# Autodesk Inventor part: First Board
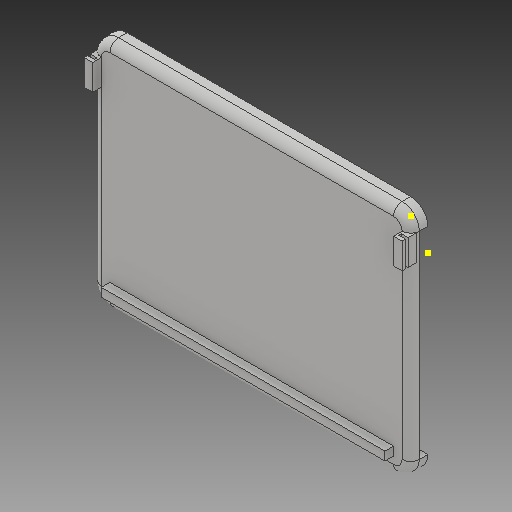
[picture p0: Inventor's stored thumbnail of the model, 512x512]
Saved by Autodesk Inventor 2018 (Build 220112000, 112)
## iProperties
Created: 2017-07
Part Number: First Board
Material: Generic
Document SubType Name: Modeling
Designer: 17046589
Density: 1 g/cm^3
Appearance: Default
Mass: 1188.89 g
Surface Area: 2386.5 cm^2
Volume: 1188.89 cm^3
Author: 17046589
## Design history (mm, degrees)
sketch "Sketch1"
  geometry: L1 (0, 0)-(-270, 0); L2 (-270, 0)-(-270, 370); L3 (-270, 370)-(0, 370); L4 (0, 370)-(0, 0)
  constraints: 8 end point, 2 parallel, 1 horizontal, 1 perpendicular
  dimensions: "d0" = 270 distance of L2.end L3.end; "d1" = 370 distance of L1.end L2.end
extrude "Extrusion1" new body sketch "Sketch1" distance "d2" = 20; taper "d3" = 0 deg
fillet "Fillet1" dims "d4" = 20
fillet "Fillet2" dims "d5" = 20
fillet "Fillet3" dims "d6" = 20
fillet "Fillet4" dims "d7" = 20
fillet "Fillet5" dims "d8" = 10
sketch "Sketch2"
  geometry: L1 (0, -20)-(0, -250) reference; L2 (0, -20)-(0, -250.001); L3 (10, -20)-(10, -250) reference; L4 (370, -250)-(370, -20) reference; L5 (370, -250.001)-(370, -20); L6 (370, -20)-(0, -20); 1 further point; 1 other entity
  constraints: 6 end point, 1 collinear, 1 parallel, 1 perpendicular, 1 vertical, 3 other
extrude "Extrusion2" cut sketch "Sketch2" distance "d9" = 10; taper "d10" = 0 deg
sketch "Sketch3"
  geometry: L1 (-350, -251.554)-(-20, -251.554); L2 (-20, -260)-(-350, -260) reference; L3 (-20, -251.554)-(-20, -241.554); L4 (-20, -241.554)-(-350, -241.554); L5 (-350, -241.554)-(-350, -251.554); 1 further point
  constraints: 8 end point, 3 perpendicular, 1 parallel
  dimensions: "d11" = 10 distance of L1.end L3.end
extrude "Extrusion3" join sketch "Sketch3" distance "d12" = 10; taper "d13" = 0 deg
sketch "Sketch4"
  geometry: L1 (10, -20)-(10, -250) reference; L2 (360, -250)-(360, -20) reference; L3 (10, -36.431)-(360, -36.431); L4 (360, -36.431)-(360, -46.677); L5 (360, -46.677)-(10, -46.677); L6 (10, -46.677)-(10, -36.431); 1 further point
  constraints: 8 end point, 2 parallel, 2 point on line, 1 horizontal, 1 perpendicular
extrude "Extrusion4" join sketch "Sketch4" distance "d14" = 10; taper "d15" = 0 deg
sketch "Sketch5"
  geometry: 1 further point
sketch "Sketch6"
  geometry: C1 r 2.205 at (4.002, 20); C2 r 2.205 at (4.002, 348.386); 1 further point
  constraints: 2 centre point
  dimensions: "d16" = 4.41 diameter of C1; "d17" = 4.41 diameter of C2
extrude "Extrusion5" join sketch "Sketch6" distance "d18" = 26.5125; taper "d19" = 0 deg
sketch "Sketch7"
  geometry: 1 further point
sketch "Sketch8"
  geometry: L1 (-10, -20)-(-10, -250) reference; L2 (0, -20)-(-370, -20) reference; L3 (-10, -20)-(0, -20); L4 (0, -20)-(0, -50); L5 (0, -250)-(0, -20) reference; L6 (0, -50)-(-10, -50); L7 (-10, -50)-(-10, -20); L8 (-370, -20)-(-359.909, -20); L9 (-360, -250)-(-360, -20) reference; L10 (-360, -20)-(-360, -50); L11 (-360, -50)-(-370, -50); L12 (-370, -20)-(-370, -250) reference; L13 (-370, -50)-(-370, -20); 1 further point
  constraints: 16 end point, 3 perpendicular, 3 point on line, 2 collinear
  dimensions: "d20" = 30 distance of L2.start L4.end; "d21" = 30 distance of L9.end L10.end
extrude "Extrusion6" join sketch "Sketch8" distance "d22" = 10; taper "d23" = 0 deg
sketch "Sketch9"
  geometry: L1 (-370, -20)-(-370, -250) reference; L2 (-370, -20)-(-360.062, -20); L3 (0, -20)-(-370, -20) reference; L4 (-360, -250)-(-360, -20) reference; L5 (-360, -20)-(-360, -50); L6 (-360, -50)-(-370, -50); L7 (-370, -50)-(-370, -20); 1 further point
  constraints: 8 end point, 2 point on line, 1 collinear, 1 perpendicular
  dimensions: "d24" = 30 distance of L4.end L5.end
extrude "Extrusion7" join sketch "Sketch9" distance "d25" = 10; taper "d26" = 0 deg
sketch "Sketch10"
  geometry: L1 (370, -20)-(370, -50) reference; L2 (370, -50)-(370, -20); L3 (360, -20)-(370, -20) reference; L4 (370, -20)-(360, -20); L5 (360, -50)-(360, -20) reference; L6 (360, -20)-(360, -20); L7 (370, -50)-(360, -50) reference; L8 (360, -20)-(360, -50); L9 (360, -50)-(370, -50); 1 further point
  constraints: 10 end point, 4 collinear, 1 perpendicular
extrude "Extrusion8" join sketch "Sketch10" distance "d27" = 7; taper "d28" = 0 deg
sketch "Sketch11"
  geometry: L1 (0, -50)-(0, -20) reference; L2 (0, -20)-(0, -50); L3 (10, -50)-(0, -50) reference; L4 (0, -50)-(10, -50); L5 (0, -20)-(10, -20) reference; L6 (10, -50)-(10, -20); L7 (10, -20)-(0, -20); 1 further point
  constraints: 8 end point, 2 collinear, 2 perpendicular
extrude "Extrusion9" join sketch "Sketch11" distance "d29" = 7; taper "d30" = 0 deg
sketch "Sketch12"
  geometry: L1 (10, 10)-(-7, 10) reference; L2 (6.02, 10)-(2.97, 10); L3 (2.97, 10)-(2.97, 2.18); L4 (2.97, 2.18)-(6.02, 2.18); L5 (6.02, 2.18)-(6.02, 10); L6 (6.02, -360)-(2.97, -360); L7 (2.97, -360)-(2.97, -352.18); L8 (2.97, -352.18)-(6.02, -352.18); L9 (6.02, -352.18)-(6.02, -360); 1 further point
  constraints: 16 end point, 4 parallel, 3 point on line, 2 horizontal, 2 perpendicular
  dimensions: "d31" = 3.05 distance of L4.end L3.end; "d32" = 7.82 distance of L3.end L2.end; "d33" = 7.82 distance of L6.end L7.end
extrude "Extrusion10" cut sketch "Sketch12" distance "d34" = 40; taper "d35" = 0 deg
body "Solid1"
